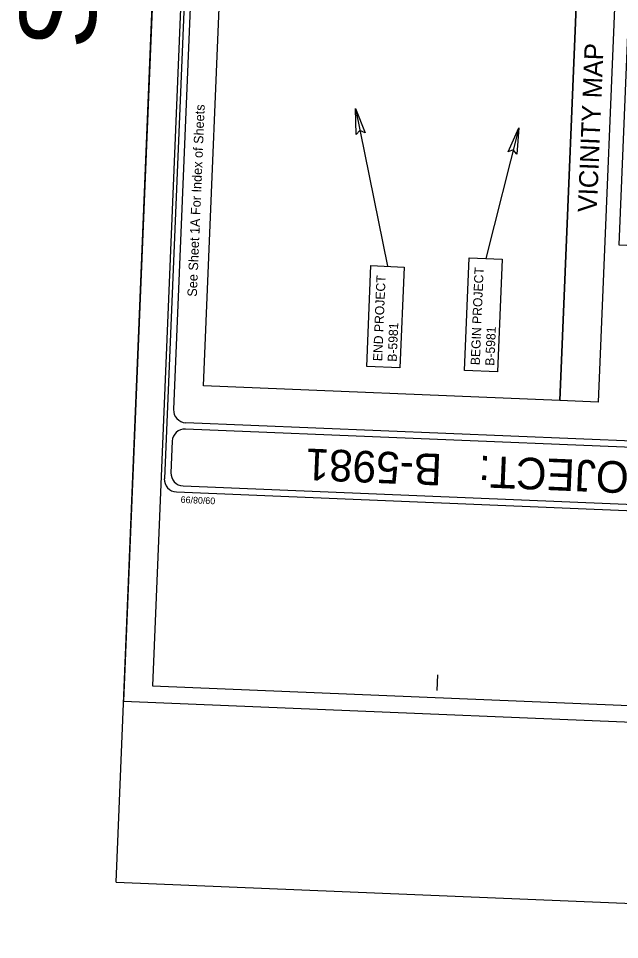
# Model space of a CAD drawing. Extents: x 2264506 to 2267635, y 507918 to 512596.
# Drawn here: x 2264506 to 2265694, y 507918 to 509740 of the extents above; entities that cross this region are included whole.
import ezdxf

# ---------------------------------------------------------------- set-up
doc = ezdxf.new("R2010")
doc.units = 0
for name, color, linetype in [('COGO Default Parcel', 7, 'Continuous'), ('Default', 7, 'Continuous'), ('Exist Structure Minor Drop Inlet Cogo Number', 7, 'Continuous'), ('Matchline', 7, 'Continuous'), ('Prop EOT Dash', 7, 'Continuous'), ('Prop Horizontal Alignment Station Label', 7, 'Continuous'), ('Prop Horizontal Alignment Tick Label', 7, 'Continuous'), ('Prop Horizontal Alignment Tick Large', 7, 'Continuous'), ('Prop Structure Anchor Unit CELL', 7, 'Continuous'), ('Scratch_Level_1', 7, 'Continuous')]:
    doc.layers.add(name, color=color, linetype=linetype)

msp = doc.modelspace()

# ---------------------------------------------------------------- linework, layer by layer
at = {"layer": 'COGO Default Parcel'}
msp.add_lwpolyline([(2266744.1, 509248.2), (2266800.3, 510607.5), (2265959.7, 510642.3), (2265949.8, 510403.2), (2265738.5, 510412), (2265692.2, 509291.7)], close=True, dxfattribs=at)
at = {"layer": 'Default'}
for points in [[(2265617.1, 509986.5), (2265575.7, 508983.7), (2264871.3, 509012.8), (2264912.8, 510015.6)], [(2265575.7, 508983.7), (2265617.1, 509986.5), (2265692.9, 509983.3), (2265651.5, 508980.6)]]:
    msp.add_lwpolyline(points, close=True, dxfattribs=at)
at = {"layer": 'Exist Structure Minor Drop Inlet Cogo Number'}
for p, q in [((2265171.9, 509561.4), (2265235.4, 509249.2)), ((2265494.7, 509522.8), (2265429.3, 509264.9))]:
    msp.add_line(p, q, dxfattribs=at)
for points in [[(2265387.3, 509043), (2265396.5, 509266.3), (2265462.1, 509263.6), (2265452.9, 509040.3)], [(2265194.3, 509051), (2265202.6, 509250.5), (2265268.2, 509247.8), (2265259.9, 509048.3)]]:
    msp.add_lwpolyline(points, close=True, dxfattribs=at)
at = {"layer": 'Matchline'}
for q in [(2264872.5, 512237.4), (2267446.4, 507917.5)]:
    msp.add_line((2264698.7, 508031), q, dxfattribs=at)
at = {"layer": 'Prop Horizontal Alignment Station Label'}
for p, q in [((2266922.1, 508853.6), (2264836.3, 508939.8)), ((2267383.7, 508822), (2264835.8, 508927.3)), ((2265333.7, 508410), (2265335, 508441.3)), ((2265333.7, 508410), (2265335, 508441.3))]:
    msp.add_line(p, q, dxfattribs=at)
for points in [[(2264947, 512525.8), (2264794.2, 508828.9)], [(2264959, 512512.8), (2264812.4, 508965.8)], [(2264809.9, 508903.3), (2264807.2, 508840.9)], [(2264818.2, 508802.9), (2267391, 508696.6)], [(2264818.2, 508802.9), (2267391, 508696.6)], [(2264831.2, 508814.9), (2267379, 508709.6)]]:
    msp.add_lwpolyline(points, dxfattribs=at)
for centre, start, end in [((2264837.3, 508964.8), 177.6342, 267.6342), ((2264834.7, 508902.3), 87.6342, 177.6342), ((2264832.1, 508839.9), 177.6342, 267.6342), ((2264819.1, 508827.9), 177.6342, 267.6342)]:
    msp.add_arc(centre, 25, start, end, dxfattribs=at)
at = {"layer": 'Prop Horizontal Alignment Tick Label'}
msp.add_lwpolyline([(2267406.5, 508310.6), (2267578.5, 512473.3), (2264943, 512582.2), (2264771, 508419.5)], close=True, dxfattribs=at)
at = {"layer": 'Prop Horizontal Alignment Tick Large'}
msp.add_lwpolyline([(2264887.3, 512595.8), (2264713.6, 508389.4), (2267461.2, 508275.9), (2267635, 512482.3)], close=True, dxfattribs=at)
at = {"layer": 'Scratch_Level_1'}
for points in [[(2265173.4, 509510), (2265171.9, 509561.4), (2265190.9, 509513.3), (2265180.8, 509517.8)], [(2265473.8, 509475.9), (2265494.7, 509522.8), (2265490.9, 509471.2), (2265483.7, 509479.7)]]:
    msp.add_lwpolyline(points, close=True, dxfattribs=at)

# ---------------------------------------------------------------- texts
at = {"layer": 'Default'}
msp.add_text('VICINITY MAP', height=37.5, rotation=87.6342, dxfattribs=at).set_placement((2265648.8, 509355.6))
at = {"layer": 'Prop EOT Dash'}
msp.add_text('SCALE 125:1', height=150, rotation=87.6342, dxfattribs=at).set_placement((2264656.1, 509677.7))
at = {"layer": 'Prop Horizontal Alignment Station Label'}
for s, height, rotation, p in [('See Sheet 1A For Index of Sheets', 18.75, 87.6342, (2264858.4, 509188.8)), ('See Sheet 1A For Index of Sheets', 18.75, 87.6342, (2264858.4, 509188.8)), ('B-5981', 62.5, 177.6342, (2265344.1, 508877.8)), ('TIP PROJECT:', 62.5, 177.6342, (2265982.5, 508851.4)), ('09/08/99', 13.12, 177.6342, (2264895, 508791.6))]:
    msp.add_text(s, height=height, rotation=rotation, dxfattribs=at).set_placement(p)
at = {"layer": 'Prop Structure Anchor Unit CELL'}
for s, p in [('BEGIN PROJECT ', (2265417.5, 509053.4)), ('END PROJECT', (2265224.6, 509061.3)), ('B-5981', (2265253.4, 509060.1)), ('B-5981', (2265446.3, 509052.2))]:
    msp.add_text(s, height=18, rotation=87.6342, dxfattribs=at).set_placement(p)

doc.saveas('drawing.dxf')
